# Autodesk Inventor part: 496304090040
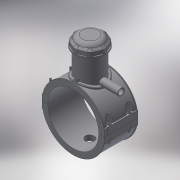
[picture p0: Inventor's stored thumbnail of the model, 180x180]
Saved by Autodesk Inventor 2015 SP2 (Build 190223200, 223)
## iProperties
Created: 2017-07
Part Number: 496304090040
Material: Generic
Description: PLASSON TAPPING SADDLE 90x40
Document SubType Name: Modeling
Designer: KIM
Mass: 607.806 g
Surface Area: 1584.18 cm^2
Volume: 607.806 cm^3
Density: 1 g/cm^3
Appearance: Default
Author: KIM
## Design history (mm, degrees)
derived "496304.ipt"
feature "Solid1::496304.ipt"
feature "Solid2::496304.ipt"
feature "Solid4::496304.ipt"
feature "Solid5::496304.ipt"
tag "TaggingFeature1"
body "Solid1"
body "Solid2"
other parameters: "d2" = 126, "d3" = 22.5, "d4" = 118, "d5" = 0, "d6" = 0.1, "d8" = 0, "d19" = 6, "d20" = 6, "d21" = 70.8, "d23" = 0, "d24" = 35.4, "d26" = 0, "d29" = 3, "d31" = 6, "d32" = 0, "d33" = 0, "d34" = 0.6, "d40" = 58.032, "d41" = 63, "d43" = 0, "d45" = 0, "d47" = 126.6, "d70" = 15, "d72" = 0, "d73" = 6, "d75" = 5, "d76" = 0, "d77" = 4.5, "d78" = 75, "d79" = 15, "d80" = 47.2, "d82" = 5 deg, "d84" = 4, "d85" = 14, "d86" = 0, "d87" = 3, "d88" = 0, "d89" = 1, "d90" = 1, "d91" = 94.4, "d92" = 0, "d93" = 0.5, "d94" = 47.36842, "d96" = 113.832, "d97" = 2.36, "d98" = 0, "d102" = 0.9, "d120" = 140 deg, "d121" = 24.228, "d122" = 20 deg, "d123" = 223.2, "d124" = 66.96, "d126" = 0, "d143" = 92.7, "d145" = 16.61538, "d149" = 1.35, "d150" = 18.27692, "d153" = 118, "d154" = 0, "d156" = 55.8, "d157" = 160 deg, "d159" = 4.32, "d161" = 1.35, "d162" = 70.8, "d163" = 0, "d164" = 45, "d167" = 9, "d168" = 54.43902, "d170" = 3.375, "d172" = 0, "d173" = 1, "d175" = 45, "d176" = 20 deg, "d177" = 6.3, "d178" = 21.6, "d180" = 0, "d183" = 8.64, "d184" = 5.04, "d185" = 38.35, "d186" = 38.35, "d187" = 55.8, "d188" = 6.48, "d189" = 6.3, "d190" = 0, "d191" = 83.7, "d193" = 6.3, "d194" = 4.13, "d195" = 90 deg, "d197" = 0, "d199" = 0, "d200" = 10.8, "d202" = 0, "d203" = 114, "d204" = 59.85, "d205" = 44.1, "d206" = 53.55, "d207" = 85.5, "d208" = 88.92, "d209" = 106.02, "d210" = 54.18, "d211" = 63, "d212" = 50.4, "d213" = 0.9, "d216" = 0, "d217" = 9, "d218" = 9, "d219" = 1.8, "d224" = 0, "d230" = 5.4, "d233" = 6, "d236" = 63, "d237" = 35.4, "d238" = 6.02433, "d240" = 35.4, "d241" = 35.4, "d242" = 35.4, "d243" = 6, "d244" = 35.4, "d245" = 35.4, "d246" = 35.4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
